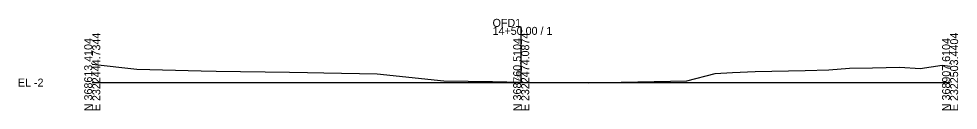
# Model space of a CAD drawing. Extents: x -26 to 303, y -10 to 14048.
# Drawn here: x -25.7 to 302.8, y 8990.3 to 9022.4 of the extents above; entities that cross this region are included whole.
import ezdxf

# ---------------------------------------------------------------- set-up
doc = ezdxf.new("R2010")
doc.units = 0
for name, color, linetype in [('RD_GPK_XS_Cell', 7, 'Continuous'), ('RD_XS_ExGround', 7, 'Continuous'), ('RD_XS_TX_Elev_EX', 7, 'Continuous')]:
    doc.layers.add(name, color=color, linetype=linetype)

msp = doc.modelspace()

# ---------------------------------------------------------------- linework, layer by layer
at = {"layer": 'RD_GPK_XS_Cell'}
for p, q in [((150, 9000), (150, 9019.53)), ((0, 9000), (150, 9000)), ((150, 9000), (300, 9000))]:
    msp.add_line(p, q, dxfattribs=at)
at = {"layer": 'RD_XS_ExGround'}
for p, q in [((0, 9006.51), (15.58, 9004.7)), ((257.61, 9004.46), (264.85, 9005.1)), ((264.85, 9005.1), (272.91, 9005.16)), ((272.91, 9005.16), (282.44, 9005.38)), ((282.44, 9005.38), (289.57, 9004.9)), ((289.57, 9004.9), (297.28, 9006.14)), ((297.28, 9006.14), (300, 9005.8)), ((15.58, 9004.7), (38.07, 9004.18)), ((38.07, 9004.18), (43.3, 9004.05)), ((43.3, 9004.05), (68.95, 9003.64)), ((68.95, 9003.64), (75.3, 9003.5)), ((75.3, 9003.5), (81.04, 9003.41)), ((81.04, 9003.41), (99.59, 9003.04)), ((99.59, 9003.04), (122.94, 9000.63)), ((207.9, 9000.65), (217.81, 9003.18)), ((217.81, 9003.18), (223.89, 9003.54)), ((223.89, 9003.54), (231.81, 9003.83)), ((231.81, 9003.83), (249.35, 9004.19)), ((249.35, 9004.19), (257.61, 9004.46)), ((122.94, 9000.63), (139.99, 9000.39)), ((139.99, 9000.39), (150, 9000.17)), ((150, 9000.17), (173.53, 8999.89)), ((173.53, 8999.89), (207.9, 9000.65))]:
    msp.add_line(p, q, dxfattribs=at)

# ---------------------------------------------------------------- texts
at = {"layer": 'RD_GPK_XS_Cell'}
for s, p in [('OFD1', (140, 9019.53)), ('14+50.00 / 1', (140, 9016.73)), ('EL -2', (-26, 8998.6))]:
    msp.add_text(s, height=2.8, dxfattribs=at).set_placement(p)
for s, p in [('N 368613.4104', (0, 8990)), ('E 2322444.7344', (2.8, 8990)), ('N 368760.5104', (150, 8990)), ('E 2322474.0874', (152.8, 8990)), ('N 368907.6104', (300, 8990)), ('E 2322503.4404', (302.8, 8990))]:
    msp.add_text(s, height=2.8, rotation=90, dxfattribs=at).set_placement(p)
at = {"layer": 'RD_XS_TX_Elev_EX'}
msp.add_text('-1.83', height=1, rotation=90, dxfattribs=at).set_placement((149.5, 9001.17))

doc.saveas('drawing.dxf')
